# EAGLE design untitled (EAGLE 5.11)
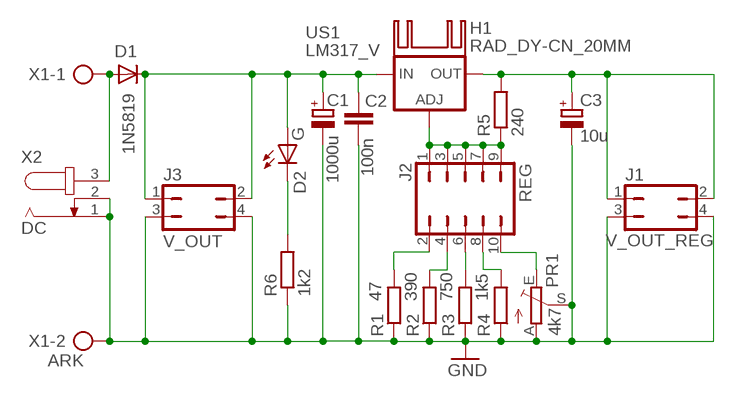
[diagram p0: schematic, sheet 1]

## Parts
C1  1000u  CPOL-EUE5-13  [E5-13]
C2  100n  C-EU050-030X075  [C050-030X075]
C3  10u  CPOL-EUE2.5-6  [E2,5-6]
D1  1N5819  DIODE-D-5  [D-5]
D2  G  LED3MM  [LED3MM]
H1  RAD_DY-CN_20MM  [RAD_DY-CN_20MM]
J1  V_OUT_REG  JP2Q  [JP2Q]
J2  REG  JP5Q  [JP5Q]
J3  V_OUT  JP2Q  [JP2Q]
PR1  4k7  TRIM_EU-S64Y  [S64Y]
R1  47  R-EU_0207/10  [0207/10]
R2  390  R-EU_0207/10  [0207/10]
R3  750  R-EU_0207/10  [0207/10]
R4  1k5  R-EU_0207/10  [0207/10]
R5  240  R-EU_0207/10  [0207/10]
R6  1k2  R-EU_0207/10  [0207/10]
US1  LM317_V  [317_V]
X1  ARK  AK500/2  [AK500/2]
X2  DC  JACK-PLUG1  [SPC4078]

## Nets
1V5: J2.2 R1.2
3V3: J2.4 R2.2
9V: J2.8 R4.2
GND: C1.- C2.2 C3.- J1.3 J1.4 J3.3 J3.4 PR1.A PR1.S R1.1 R2.1 R3.1 R4.1 R6.1 X1.2 X2.1 X2.2
N$1: D2.K(C) R6.2
N$2: J2.1 J2.3 J2.5 J2.7 J2.9 R5.1 US1.1(ADJ)
N$3: J2.6 R3.2
N$9: C1.+ C2.1 D1.C D2.A J3.1 J3.2 US1.3(IN)
N$12: D1.A X1.1 X2.3
VOUT: C3.+ J1.1 J1.2 R5.2 US1.2(OUT)
VREG: J2.10 PR1.E

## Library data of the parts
C1 C3 = rcl:CPOL-EU: POLARIZED CAPACITOR, European symbol
C2 = rcl:C-EU: CAPACITOR, European symbol
D1 = diode:DIODE-: DIODE
D2 = led:LED: LED
H1 = radiator:RAD_DY-CN_20MM: Radiator, profil DY-CN; dl=20mm szer=15mm wys=11mm
J1 J3 = jumper:JP2Q: JUMPER
J2 = jumper:JP5Q: JUMPER
PR1 = pot:TRIM_EU-: POTENTIOMETER
R1-R6 = rcl:R-EU_: RESISTOR, European symbol
US1 = v-reg:LM317_V: VOLTAGE REGULATOR
X1 = con-ptr500:AK500/2: CONNECTOR; OC_FARNELL: unknown; OC_NEWARK: unknown
X2 = con-jack:JACK-PLUG: DC POWER JACK Power Jack, DC, Right Angle, Through Hole, Rated 5A at 16VDC, PC Terminals Distributor: Farnell (www.Farnell.de) Drawing: 84N1161.pdf / 84N1162.pdf Manufacturer: SPC Technology (www.spctechnology.com) Type: SPC4077 / SPC 4078; OC_FARNELL: unknown; OC_NEWARK: unknown

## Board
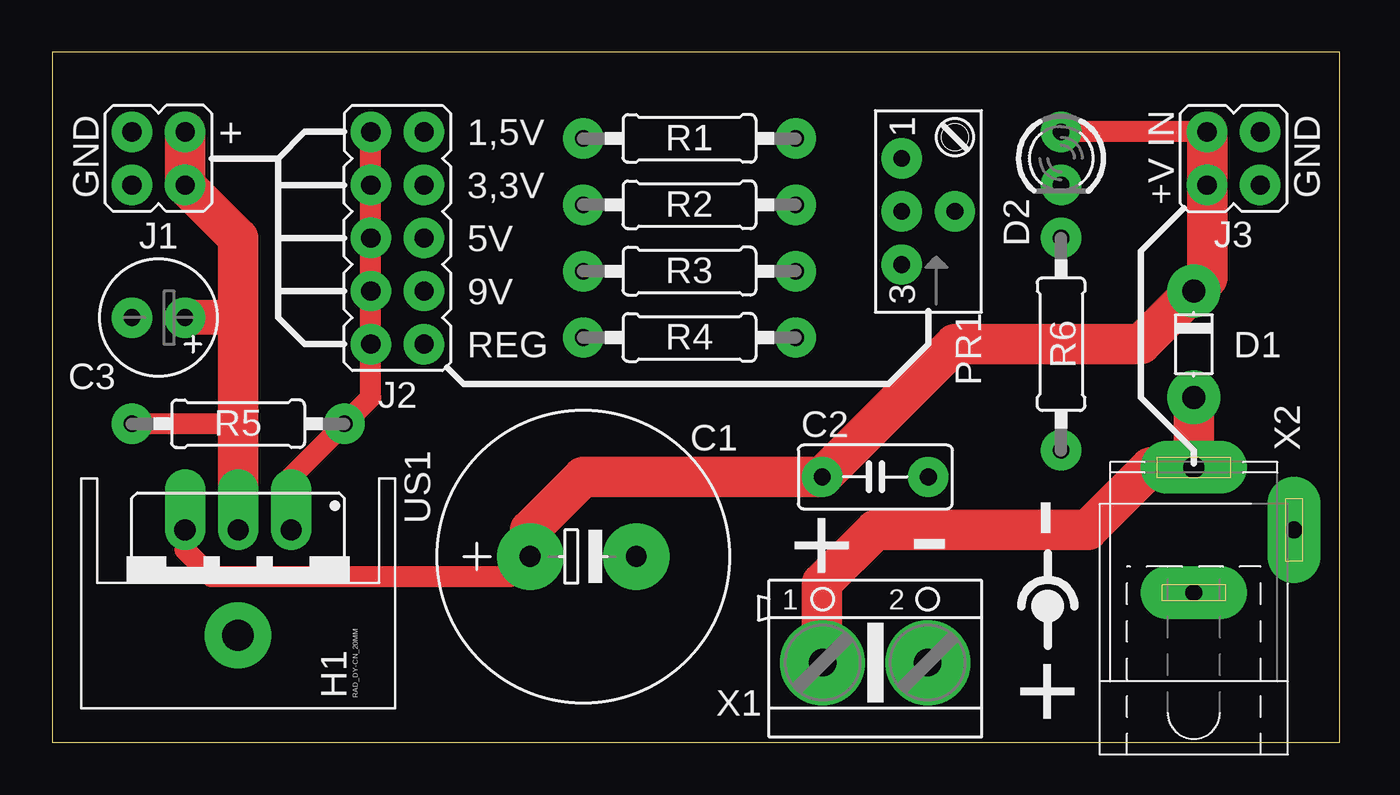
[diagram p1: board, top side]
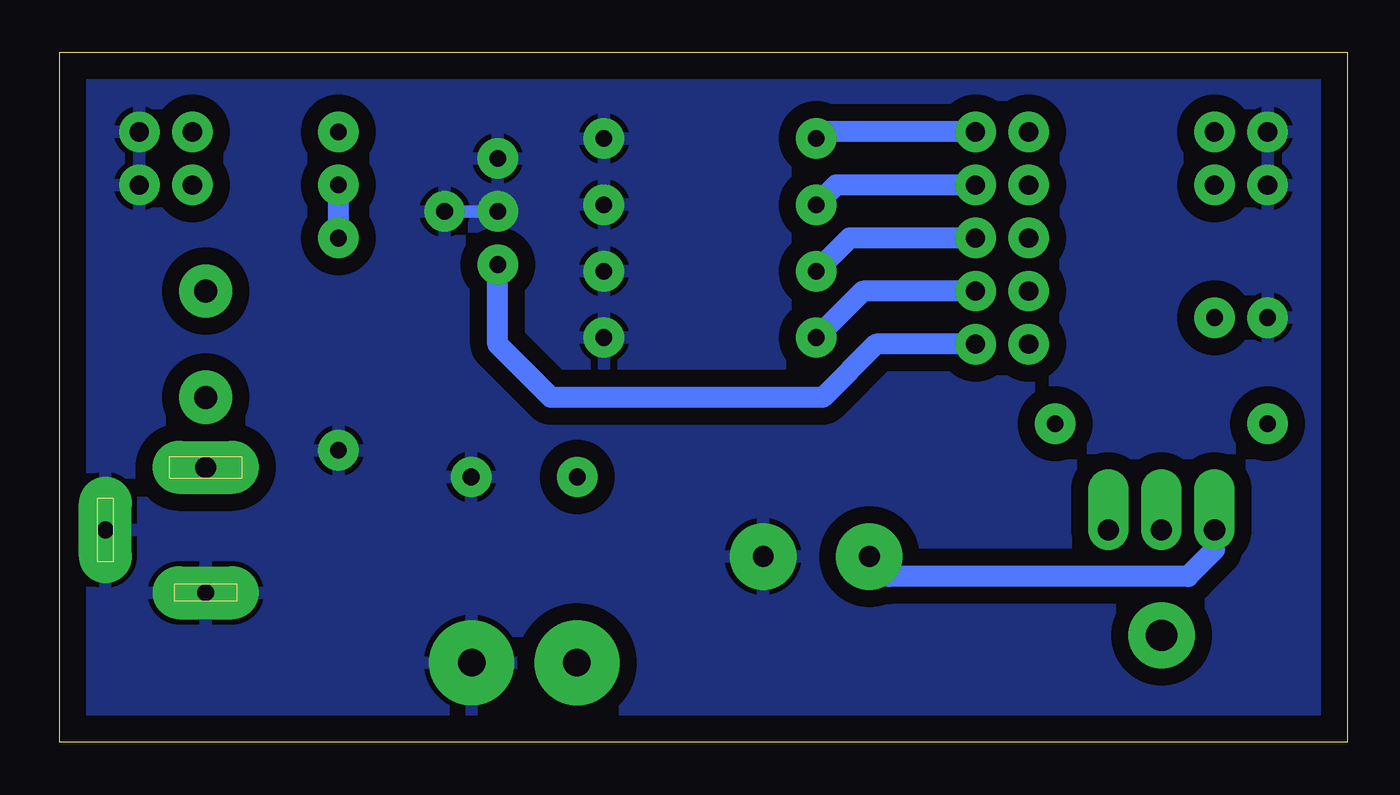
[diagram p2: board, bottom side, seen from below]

Size 61.59 x 33.02 mm. Coordinates in mm from the lower left corner, seen from the top.
Outline: 0,0 61.59,0 61.59,33.02 0,33.02 0,0
Copper layers (1*16): Top 0.035mm / dielectric 1.5mm / Bottom 0.035mm
Design rules "default *": minimum track width 10mil, minimum drill 24mil, track to track 8mil, track to pad 8mil, pad to pad 8mil, via to via 8mil, smd to smd 8mil, copper to edge 50mil, drill to drill 8mil, minimum pad ring 10mil, minimum via ring 8mil, stop-mask expansion 4mil, vias tented up to drill 0mil, thermal gap 10mil

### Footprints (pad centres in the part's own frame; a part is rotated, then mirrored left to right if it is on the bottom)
E5-13 = drill 1 pad 3.175 round: + -2.54,0; - 2.54,0
C050-030X075 = drill 0.8 pad 1.93 round: 1 -2.54,0; 2 2.54,0
E2,5-6 = drill 0.8 pad 1.93 round: + -1.27,0; - 1.27,0
D-5 = drill 1.1 pad 2.54 round: A 2.54,0; C -2.54,0
LED3MM = drill 0.8 pad 1.93 round: A -1.27,0; K 1.27,0
RAD_DY-CN_20MM = drill 1.5 pad 3.175 round: P$1 0,-2.5
JP2Q = drill 0.914 pad 1.93 round: 1 -1.27,-1.27; 2 -1.27,1.27; 3 1.27,-1.27; 4 1.27,1.27
JP5Q = drill 0.914 pad 1.93 round: 1 -5.08,-1.27; 2 -5.08,1.27; 3 -2.54,-1.27; 4 -2.54,1.27; 5 0,-1.27; 6 0,1.27; 7 2.54,-1.27; 8 2.54,1.27; 9 5.08,-1.27; 10 5.08,1.27
S64Y = drill 0.8 pad 1.93 round: A 2.54,1.27; E -2.54,1.27; S 0,-1.27
0207/10 = drill 0.8 pad 1.93 round: 1 -5.08,0; 2 5.08,0
317_V = drill 1.016 pad 1.93 offset: 1 -2.54,-2.54; 2 0,-2.54; 3 2.54,-2.54
AK500/2 = drill 1.321 pad 4.064 round: 1 -2.515,0; 2 2.515,0
SPC4078 = drill 0.8 pad 2.54 long: 1 -3,0; 2 0,-4.8 | drill 1 pad 2.54 long: 3 3,0

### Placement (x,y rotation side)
C1  25.4,8.89 0 top
C2  39.37,12.7 0 top
C3  5.08,20.32 180 top
D1  54.61,19.05 270 top
D2  48.26,27.94 270 top
H1  8.89,7.62 0 top
J1  5.08,27.94 180 top
J2  16.51,24.13 270 top
J3  56.52,27.94 0 top
PR1  41.91,25.4 90 top
R1  30.48,28.89 180 top
R2  30.48,25.72 180 top
R3  30.48,22.54 180 top
R4  30.48,19.37 180 top
R5  8.89,15.24 180 top
R6  48.26,19.05 90 top
US1  8.89,7.62 180 top
X1  39.37,3.81 0 top
X2  54.61,10.16 90 top

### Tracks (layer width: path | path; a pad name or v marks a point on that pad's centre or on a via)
1V5
  Bottom 1.016: J2.2 25.08,29.21 R1.2
3V3
  Bottom 1.016: J2.4 24.45,26.67 R2.2
9V
  Bottom 1.016: J2.8 23.18,21.59 R4.2
GND  (via drill 0.8 pad 1.93)
  Bottom 0.61: v40.64,25.4 PR1.S
  pour Bottom (isolate 0.813): 0,33.02 61.59,33.02 61.59,0 0,0
N$1
  Bottom 1.016: R6.2 D2.K
N$2
  Top 1.016: J2.1 J2.3 J2.5 J2.7 J2.9 15.24,16.51 R5.1 11.43,12.7 US1.1
N$3
  Bottom 1.016: J2.6 23.81,24.13 R3.2
N$9
  Top 1.016: US1.3 6.35,9.21 7.62,7.94 21.91,7.94 C1.+ | J3.2 D2.A
  Top 1.93: C1.+ 22.86,10.16 25.4,12.7 C2.1 43.18,19.05 52.07,19.05 D1.C 55.24,22.23 J3.1 J3.2
  Bottom 1.016: C1.+ 21.91,7.94 7.62,7.94 6.35,9.21 US1.3
N$12
  Top 1.676: X1.1 36.83,3.81
  Top 1.93: 36.83,3.81 36.83,7.62 39.37,10.16 49.53,10.16 52.53,13.16 X2.3 D1.A
VOUT
  Top 1.016: 8.89,15.24 R5.2
  Top 1.676: 8.89,20.32 C3.+
  Top 1.93: J1.1 J1.2 8.89,24.13 8.89,20.32 8.89,15.24 US1.2
VREG
  Bottom 1.016: J2.10 22.54,19.05 25.08,16.51 38.1,16.51 40.64,19.05 PR1.E

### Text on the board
tNames: + | 1,5V | GND | 3,3V | +V IN | GND | 5V | 9V | REG | - | + | - | +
